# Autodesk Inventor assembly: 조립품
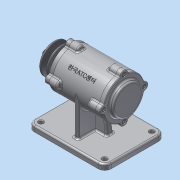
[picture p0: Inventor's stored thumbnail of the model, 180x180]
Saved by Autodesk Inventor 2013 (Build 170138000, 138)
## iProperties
Created: 2015-12
Part Number: 조립품
Document SubType Name: Assembly
Designer: dgall
Author: dgall
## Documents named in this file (11)
- C:\Users\dgall\Desktop\451207V1032\조립품.iam
- C:\Users\dgall\Desktop\451207V1032\V-벨트풀리.ipt
- C:\Users\dgall\Desktop\451207V1032\너트 M12x1.25.ipt
- C:\Users\dgall\Desktop\451207V1032\베어링 6204.ipt
- C:\Users\dgall\Desktop\451207V1032\본체.ipt
- C:\Users\dgall\Desktop\451207V1032\볼트 M4 x 12.ipt
- C:\Users\dgall\Desktop\451207V1032\오일실.ipt
- C:\Users\dgall\Desktop\451207V1032\축.ipt
- C:\Users\dgall\Desktop\451207V1032\커버.ipt
- C:\Users\dgall\Desktop\451207V1032\커버2.ipt
- C:\Users\dgall\Desktop\451207V1032\키(4 x 4 x 12).ipt
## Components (6 placed, 5 different names)
1. V-벨트풀리:1
2. KS B 1012 클래스 1 일반 - 미터 M12x1.25:1
3. KS B 2023 6204 - 20 x 47 x 14:1
4. KS B 2804 D D - 20 32 8:1
5. KS B 1311 (I) 4 x 4 x 12:1
6. KS B 2023 6204 - 20 x 47 x 14:2
